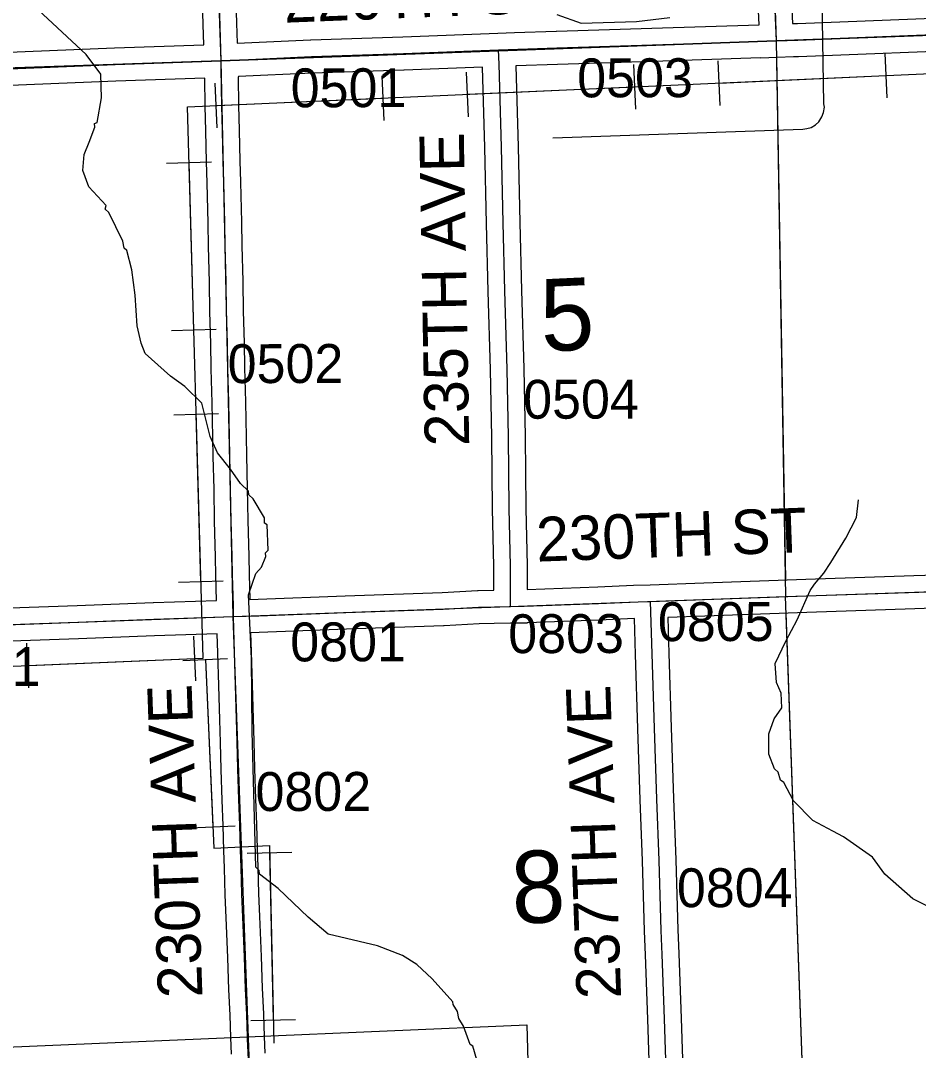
# Model space of a CAD drawing. Extents: x 128.7 to 185.5, y -21.4 to 12.6.
# Drawn here: x 146.826 to 148.442, y -9.105 to -7.251 of the extents above; entities that cross this region are included whole.
import ezdxf

# ---------------------------------------------------------------- set-up
doc = ezdxf.new("R2010")
doc.units = 0
for name, color, linetype in [('tdCoCityStreetMajor', 7, 'Continuous'), ('tdCoCorpBndry', 7, 'Continuous'), ('tdCoDirctArrow', 7, 'Continuous'), ('tdCoHydroRiver', 7, 'Continuous'), ('tdCoPipe', 7, 'Continuous'), ('tdCoSecRdNmbr', 7, 'Continuous'), ('tdCoSecRdTxt', 7, 'Continuous'), ('tdCoSecRteBand', 7, 'Continuous'), ('tdCoSecRteCL', 7, 'Continuous'), ('tdCoSectLine', 7, 'Continuous'), ('tdCoSectLinePart', 7, 'Continuous'), ('tdCoSectNmbr', 7, 'Continuous'), ('tdCoSurfAsphalt', 7, 'Continuous'), ('tdCoSurfGravel', 7, 'Continuous'), ('tdCoTwpBndryShd', 7, 'Continuous')]:
    doc.layers.add(name, color=color, linetype=linetype)

msp = doc.modelspace()

# ---------------------------------------------------------------- linework, layer by layer
at = {"layer": 'tdCoCityStreetMajor'}
msp.add_lwpolyline([(147.2541, -9.648), (147.254, -9.6415), (147.2536, -9.6294), (147.2528, -9.5999), (147.252, -9.5812), (147.2505, -9.5406), (147.2501, -9.5269), (147.2493, -9.4988), (147.2478, -9.4468), (147.2475, -9.4358), (147.2472, -9.423), (147.2462, -9.3809), (147.2445, -9.3207), (147.2417, -9.2576), (147.239, -9.1803), (147.2367, -9.133), (147.2343, -9.0837), (147.2342, -9.0804)], dxfattribs=at)
at = {"layer": 'tdCoCorpBndry'}
msp.add_lwpolyline([(146.2705, -10.129), (146.2661, -9.9803), (146.2641, -9.8974), (146.2456, -9.3614), (146.2436, -9.283), (146.2422, -9.2521), (146.239, -9.1399), (146.2385, -9.1228), (147.2342, -9.0804), (147.737, -9.0589), (147.7522, -9.6071), (147.7531, -9.6384), (147.7717, -10.312)], dxfattribs=at)
at = {"layer": 'tdCoDirctArrow'}
msp.add_lwpolyline([(147.7837, -7.4626), (148.2339, -7.4469), (148.2414, -7.4457), (148.2487, -7.4438), (148.2565, -7.439), (148.2626, -7.4333), (148.268, -7.4248), (148.2713, -7.417), (148.273, -7.4074), (148.272, -7.4011), (148.2668, -7.0998)], dxfattribs=at)
at = {"layer": 'tdCoHydroRiver'}
for points in [[(147.647, -9.1218), (147.6398, -9.0968), (147.635, -9.0938), (147.6229, -9.061), (147.6145, -9.0471), (147.6125, -9.0345), (147.6042, -9.0222), (147.6041, -9.0175), (147.5664, -8.9761), (147.5388, -8.9502), (147.513, -8.9337), (147.4682, -8.9162), (147.3791, -8.8954), (147.3434, -8.865), (147.2896, -8.8131), (147.2557, -8.7874), (147.2554, -8.7811), (147.2489, -8.775), (147.2425, -8.5306), (147.2414, -8.3996), (147.236, -8.2846), (147.249, -8.2463), (147.2596, -8.2349), (147.2669, -8.2157), (147.2667, -8.2094), (147.2713, -8.2045), (147.2698, -8.1588), (147.2649, -8.1558), (147.2646, -8.1464), (147.2446, -8.1123), (147.2364, -8.1047), (147.2362, -8.0984), (147.2216, -8.0846), (147.2034, -8.0584), (147.1803, -8.0292), (147.1667, -7.9996), (147.1521, -7.9401), (147.1211, -7.9096), (147.0953, -7.8915), (147.0498, -7.8504), (147.0428, -7.8317), (147.0355, -7.8004), (147.0321, -7.7452), (147.0259, -7.6997), (147.0169, -7.6652), (147.012, -7.6607), (147.01, -7.6481), (146.9846, -7.5969), (146.9781, -7.5908), (146.9795, -7.5844), (146.9484, -7.5507), (146.938, -7.5211), (146.9402, -7.4926), (146.9489, -7.4702), (146.9591, -7.443), (146.9589, -7.4367), (146.9636, -7.435), (146.9716, -7.3905), (146.9702, -7.348), (146.9438, -7.3125), (146.8575, -7.2317)], [(147.7913, -7.2403), (147.8347, -7.2562), (147.9344, -7.2528), (147.9944, -7.246)], [(148.4905, -8.8615), (148.4322, -8.8318), (148.3813, -8.7876), (148.3594, -8.7567), (148.3072, -8.7205), (148.2877, -8.7101), (148.252, -8.6906), (148.2172, -8.6553), (148.2, -8.6227), (148.1935, -8.6181), (148.1897, -8.604), (148.1831, -8.5979), (148.1725, -8.5713), (148.1725, -8.5349), (148.1824, -8.5077), (148.1959, -8.4883), (148.1951, -8.4615), (148.1866, -8.4428), (148.1839, -8.4082), (148.2031, -8.3681), (148.2239, -8.3296), (148.2474, -8.2767), (148.2549, -8.2654), (148.2716, -8.2459), (148.2846, -8.2263), (148.3115, -8.1828), (148.3308, -8.1458), (148.3344, -8.1141)]]:
    msp.add_lwpolyline(points, dxfattribs=at)
at = {"layer": 'tdCoPipe'}
for p, q in [((148.3859, -7.3904), (148.3823, -7.3099)), ((147.9331, -7.4107), (147.9294, -7.3302)), ((148.085, -7.4039), (148.0814, -7.3235)), ((147.4802, -7.4311), (147.4766, -7.3505)), ((147.6322, -7.4243), (147.6286, -7.3439)), ((147.1794, -7.4446), (147.1758, -7.3642)), ((147.1692, -7.506), (147.0886, -7.5083)), ((147.1777, -7.8071), (147.0973, -7.8094)), ((147.182, -7.9591), (147.1014, -7.9614)), ((147.1905, -8.2602), (147.1101, -8.2625)), ((146.8403, -8.4523), (146.8369, -8.3719)), ((147.1412, -8.4396), (147.1378, -8.3591)), ((147.118, -8.403), (147.1984, -8.3995)), ((147.1313, -8.7039), (147.2119, -8.7004)), ((147.2336, -8.7497), (147.3141, -8.7479)), ((147.2402, -9.0508), (147.3208, -9.049))]:
    msp.add_line(p, q, dxfattribs=at)
for points in [[(141.1601, -9.4052), (141.1224, -8.4625), (145.143, -8.3469), (145.1432, -8.4836), (145.1432, -8.4836), (147.1541, -8.3987), (147.1541, -8.3987), (147.1261, -7.4066), (149.2539, -7.3111), (149.2196, -6.4561), (150.4341, -6.4227), (150.6653, -6.4146), (150.7655, -6.4047), (150.7905, -6.3931), (150.9328, -6.2039), (151.0021, -6.1768), (151.0811, -6.1651), (151.2121, -6.1436), (151.4086, -6.1336), (151.5974, -6.1255), (151.7034, -6.1214)], [(148.0832, -7.3637), (148.3841, -7.3501)], [(147.6304, -7.384), (147.9312, -7.3705)], [(147.1776, -7.4043), (147.4784, -7.3908)], [(147.1374, -7.8082), (147.1289, -7.5072)], [(147.1502, -8.2613), (147.1417, -7.9603)], [(146.8386, -8.4121), (147.1395, -8.3993)], [(147.1463, -8.4013), (147.1463, -8.4013)], [(147.1583, -8.4013), (147.1733, -8.7407), (147.2736, -8.7357), (147.2815, -9.0919)], [(147.1583, -8.4013), (147.1716, -8.7021)], [(147.2739, -8.7488), (147.2805, -9.0499)]]:
    msp.add_lwpolyline(points, dxfattribs=at)
at = {"layer": 'tdCoSecRteBand'}
for points in [[(146.2091, -7.327), (146.3655, -7.3225), (146.617, -7.3146), (146.6171, -7.3146), (146.6172, -7.3146), (146.7166, -7.3119), (146.9946, -7.3006), (146.9946, -7.3006), (146.9947, -7.3006), (147.1555, -7.2947), (147.1541, -7.2581), (147.1541, -7.258), (147.1541, -7.2578), (147.1507, -7.1385)], [(147.2107, -7.1368), (147.2141, -7.256), (147.2154, -7.2921)], [(147.2154, -7.2921), (147.3477, -7.2858), (147.348, -7.2858), (147.3482, -7.2858), (147.5139, -7.2806), (147.6849, -7.2742), (147.7149, -7.273), (147.7149, -7.273), (147.79, -7.2702), (147.7901, -7.2702), (147.7902, -7.2702), (147.9623, -7.265), (148.1553, -7.2587), (148.1543, -7.2337)], [(148.2143, -7.2315), (148.2153, -7.2567), (148.2241, -7.2564), (148.5591, -7.2436)], [(148.5613, -7.3036), (148.2263, -7.3164), (148.2262, -7.3164), (148.2261, -7.3164), (148.2174, -7.3167), (148.1875, -7.3177), (148.1577, -7.3188), (148.1577, -7.3186), (148.1575, -7.3186), (147.9642, -7.325), (147.9642, -7.325), (147.9641, -7.325), (147.7921, -7.3302), (147.7172, -7.333), (147.7171, -7.333), (147.7212, -7.4783), (147.7212, -7.4784), (147.7212, -7.4785), (147.7242, -7.6148), (147.7276, -7.737), (147.7276, -7.737), (147.7276, -7.737), (147.7316, -7.8776), (147.7316, -7.8777), (147.7316, -7.8779), (147.7338, -7.9999), (147.7338, -8), (147.7338, -8.0001), (147.7355, -8.1292), (147.7375, -8.2322), (147.7375, -8.2325), (147.7375, -8.2328), (147.7375, -8.2749), (147.865, -8.2702), (147.9288, -8.2676), (147.9288, -8.2675), (147.929, -8.2675), (147.929, -8.2673), (147.9589, -8.2665), (148.0557, -8.2631), (148.0557, -8.2631), (148.0557, -8.2631), (148.2392, -8.2567), (148.2392, -8.2567), (148.2392, -8.2567), (148.4338, -8.25), (148.4338, -8.25), (148.4338, -8.25), (148.5512, -8.2461)], [(147.2384, -8.2929), (147.2533, -8.2924), (147.4101, -8.2867), (147.4101, -8.2867), (147.4101, -8.2867), (147.5849, -8.2808), (147.6484, -8.2772), (147.6489, -8.2771), (147.6494, -8.2771), (147.6775, -8.2764), (147.6775, -8.2331), (147.6755, -8.1303), (147.6755, -8.1302), (147.6755, -8.1301), (147.6738, -8.001), (147.6716, -7.8791), (147.6676, -7.7387), (147.6642, -7.6164), (147.6642, -7.6163), (147.6642, -7.6162), (147.6612, -7.4799), (147.6572, -7.3353), (147.516, -7.3405), (147.5159, -7.3406), (147.5158, -7.3406), (147.3504, -7.3457), (147.2177, -7.3521), (147.2177, -7.3524), (147.2177, -7.3524), (147.2177, -7.3524), (147.2173, -7.3525), (147.2182, -7.404), (147.219, -7.4485), (147.2205, -7.5042), (147.2215, -7.5418), (147.2215, -7.5419), (147.2215, -7.5419), (147.2232, -7.6143), (147.2242, -7.6564), (147.2242, -7.6564), (147.2242, -7.6564), (147.2256, -7.7205), (147.2256, -7.7206), (147.2256, -7.7208), (147.2264, -7.7742), (147.2279, -7.831), (147.2279, -7.8311), (147.2279, -7.8312), (147.2287, -7.8763), (147.2303, -7.9376), (147.2303, -7.9377), (147.2304, -7.9378), (147.2316, -8.0004), (147.2326, -8.0339), (147.2326, -8.034), (147.2326, -8.0342), (147.2338, -8.0932), (147.2338, -8.0932), (147.2338, -8.0933), (147.2349, -8.1507), (147.2365, -8.2151), (147.2365, -8.2152), (147.2365, -8.2153), (147.2371, -8.2484), (147.2384, -8.2929)], [(146.807, -8.3082), (146.9277, -8.304), (147.0645, -8.2986), (147.0646, -8.2986), (147.0647, -8.2986), (147.1785, -8.2949), (147.1772, -8.25), (147.1771, -8.2499), (147.1771, -8.2497), (147.1765, -8.2165), (147.1749, -8.1521), (147.1749, -8.152), (147.1749, -8.1519), (147.1739, -8.0944), (147.1726, -8.0356), (147.1716, -8.002), (147.1716, -8.0019), (147.1716, -8.0017), (147.1704, -7.9391), (147.1687, -7.8778), (147.1687, -7.8777), (147.1687, -7.8775), (147.1679, -7.8324), (147.1665, -7.7756), (147.1665, -7.7755), (147.1665, -7.7753), (147.1656, -7.7218), (147.1642, -7.6578), (147.1632, -7.6157), (147.1632, -7.6157), (147.1632, -7.6156), (147.1615, -7.5434), (147.1605, -7.5058), (147.1605, -7.5058), (147.1605, -7.5058), (147.1591, -7.4499), (147.1591, -7.4498), (147.1591, -7.4497), (147.1582, -7.4051), (147.1573, -7.3547), (146.997, -7.3605), (146.7188, -7.3719)], [(148.5532, -8.306), (148.4358, -8.31), (148.2413, -8.3166), (148.0578, -8.323), (147.9909, -8.3254), (147.9907, -8.3254), (147.9926, -8.3903), (147.9966, -8.5236), (148.0013, -8.6512), (148.0055, -8.7615), (148.0055, -8.7616), (148.0055, -8.7618), (148.0089, -8.8875), (148.0109, -8.9304), (148.0109, -8.9306), (148.0109, -8.9308), (148.0146, -9.0467), (148.0183, -9.1578)], [(147.9583, -9.1599), (147.9546, -9.0487), (147.9546, -9.0486), (147.9546, -9.0486), (147.9509, -8.9329), (147.949, -8.89), (147.9489, -8.8897), (147.9489, -8.8894), (147.9455, -8.7636), (147.9413, -8.6535), (147.9413, -8.6535), (147.9413, -8.6535), (147.9366, -8.5257), (147.9366, -8.5256), (147.9366, -8.5255), (147.9327, -8.3921), (147.9327, -8.3921), (147.9327, -8.3921), (147.9308, -8.3275), (147.8674, -8.3302), (147.8673, -8.3302), (147.8673, -8.3302), (147.7382, -8.3349), (147.7382, -8.335), (147.7375, -8.335), (147.7375, -8.3357), (147.7079, -8.3357), (147.6782, -8.3364), (147.6514, -8.3371), (147.588, -8.3408), (147.5876, -8.3408), (147.5873, -8.3408), (147.4122, -8.3467), (147.2554, -8.3524), (147.2553, -8.3524), (147.2553, -8.3524), (147.24, -8.3529), (147.2396, -8.3529), (147.2408, -8.3873), (147.2408, -8.3874), (147.2408, -8.3874), (147.2425, -8.4464), (147.2443, -8.5077), (147.2458, -8.5483), (147.2458, -8.5485), (147.2458, -8.5486), (147.247, -8.5973), (147.2486, -8.6523), (147.2501, -8.698), (147.2517, -8.7425), (147.2517, -8.7426), (147.2517, -8.7426), (147.2527, -8.7745), (147.2527, -8.7745), (147.2527, -8.7746), (147.2542, -8.8225), (147.2558, -8.8639), (147.2558, -8.8639), (147.2558, -8.8639), (147.2585, -8.9354), (147.2607, -8.9927), (147.2628, -9.0388), (147.2628, -9.039), (147.2628, -9.0392), (147.2641, -9.0794), (147.2651, -9.1094)], [(147.2052, -9.1113), (147.2042, -9.0813), (147.2028, -9.0413), (147.2008, -8.9952), (147.2008, -8.9952), (147.2008, -8.9951), (147.1985, -8.9378), (147.1985, -8.9377), (147.1985, -8.9377), (147.1959, -8.8662), (147.1942, -8.8247), (147.1942, -8.8246), (147.1942, -8.8244), (147.1928, -8.7764), (147.1917, -8.7446), (147.1901, -8.7001), (147.1901, -8.7), (147.1901, -8.7), (147.1887, -8.6541), (147.1887, -8.6541), (147.1887, -8.6541), (147.187, -8.599), (147.187, -8.5989), (147.187, -8.5989), (147.1858, -8.5503), (147.1843, -8.5098), (147.1843, -8.5097), (147.1843, -8.5096), (147.1825, -8.4482), (147.1825, -8.4481), (147.1825, -8.4481), (147.1809, -8.3892), (147.1797, -8.3549), (147.0667, -8.3585), (146.93, -8.364), (146.9299, -8.364), (146.9298, -8.364), (146.809, -8.3682)]]:
    msp.add_lwpolyline(points, dxfattribs=at)
at = {"layer": 'tdCoSecRteCL'}
for points in [[(148.1865, -7.2877), (148.1843, -7.2325), (148.1833, -7.1943), (148.1784, -7.0562), (148.1742, -6.9294), (148.1705, -6.8012), (148.1665, -6.6811), (148.1618, -6.5514), (148.1584, -6.4258), (148.1539, -6.2964), (148.1535, -6.2826)], [(147.1866, -7.3236), (147.1841, -7.257), (147.1807, -7.1376)], [(149.231, -8.7525), (149.23, -8.7125), (149.2266, -8.588), (149.2234, -8.4472), (149.2197, -8.3091), (149.2162, -8.1784), (149.2123, -8.0373), (149.2096, -7.9061), (149.2051, -7.7636), (149.2014, -7.6371), (149.1975, -7.4792), (149.1938, -7.3365), (149.1918, -7.2667), (149.1906, -7.2608), (149.1866, -7.2556), (149.1825, -7.2534), (149.1768, -7.2516), (149.0125, -7.2578), (148.7053, -7.2686), (148.5603, -7.2736), (148.2251, -7.2864), (148.1865, -7.2877)], [(147.6861, -7.3042), (147.7911, -7.3002), (147.9632, -7.295), (148.1865, -7.2877)], [(147.1866, -7.3236), (147.3492, -7.3157), (147.5149, -7.3106), (147.6861, -7.3042)], [(147.7075, -8.3057), (147.7075, -8.2328), (147.7055, -8.1297), (147.7038, -8.0005), (147.7016, -7.8784), (147.6976, -7.7379), (147.6942, -7.6155), (147.6912, -7.4792), (147.687, -7.3297), (147.6861, -7.3042)], [(146.18, -7.3579), (146.3665, -7.3525), (146.618, -7.3446), (146.7176, -7.3419), (146.9958, -7.3305), (147.1866, -7.3236)], [(147.2091, -8.3239), (147.2088, -8.3046), (147.2071, -8.2492), (147.2065, -8.2159), (147.2049, -8.1513), (147.2038, -8.0938), (147.2026, -8.0348), (147.2016, -8.0011), (147.2004, -7.9384), (147.1987, -7.877), (147.1979, -7.8318), (147.1965, -7.7749), (147.1956, -7.7212), (147.1942, -7.6571), (147.1932, -7.615), (147.1915, -7.5426), (147.1905, -7.505), (147.1891, -7.4491), (147.1882, -7.4045), (147.187, -7.3379), (147.1866, -7.3236)], [(147.9599, -8.2965), (148.0568, -8.2931), (148.2403, -8.2866), (148.4348, -8.28), (148.5522, -8.276)], [(147.7075, -8.3057), (147.732, -8.3051), (147.8661, -8.3002), (147.9374, -8.2972), (147.9599, -8.2965)], [(147.7531, -9.6384), (147.8537, -9.6358), (147.9635, -9.6338), (147.9857, -9.6341), (147.996, -9.6326), (148.0004, -9.63), (148.0024, -9.6236), (148.0036, -9.6162), (148.0044, -9.6088), (148.0041, -9.6035), (148.0036, -9.5949), (148.0014, -9.5439), (148.0004, -9.5182), (147.9967, -9.403), (147.993, -9.2844), (147.9883, -9.1589), (147.9846, -9.0477), (147.9809, -8.9318), (147.9789, -8.8886), (147.9755, -8.7626), (147.9713, -8.6524), (147.9666, -8.5246), (147.9627, -8.3912), (147.9599, -8.2965)], [(147.2091, -8.3239), (147.2543, -8.3224), (147.4112, -8.3167), (147.5863, -8.3108), (147.6501, -8.3071), (147.7075, -8.3057)], [(146.2136, -8.3605), (146.2886, -8.3574), (146.4181, -8.3527), (146.6482, -8.3439), (146.7157, -8.3411), (146.808, -8.3382), (146.9288, -8.334), (147.0657, -8.3286), (147.2091, -8.3239)], [(147.2342, -9.0804), (147.2328, -9.0401), (147.2308, -8.9939), (147.2285, -8.9366), (147.2258, -8.8651), (147.2242, -8.8235), (147.2228, -8.7755), (147.2217, -8.7436), (147.2201, -8.699), (147.2186, -8.6532), (147.217, -8.5981), (147.2158, -8.5494), (147.2143, -8.5087), (147.2125, -8.4473), (147.2108, -8.3883), (147.2094, -8.3464), (147.2091, -8.3239)]]:
    msp.add_lwpolyline(points, dxfattribs=at)
at = {"layer": 'tdCoSectLine'}
for points in [[(148.1531, -6.2826), (148.1861, -7.2877)], [(147.1565, -6.3208), (147.1862, -7.3236)], [(148.1861, -7.2877), (149.1912, -7.251)], [(147.1862, -7.3236), (148.1861, -7.2877)], [(148.1861, -7.2877), (148.203, -8.2879)], [(146.1796, -7.3579), (147.1862, -7.3236)], [(147.1862, -7.3236), (147.2075, -8.3239)], [(148.203, -8.2879), (149.2179, -8.2547)], [(147.2075, -8.3239), (148.203, -8.2879)], [(148.2385, -9.2881), (148.203, -8.2879)], [(146.2133, -8.3605), (147.2075, -8.3239)], [(147.2075, -8.3239), (147.2444, -9.3296)]]:
    msp.add_lwpolyline(points, dxfattribs=at)
at = {"layer": 'tdCoSectLinePart'}
for points in [[(148.1866, -7.3176), (148.2025, -8.2585)], [(148.2385, -9.2881), (148.2041, -8.3179)]]:
    msp.add_lwpolyline(points, dxfattribs=at)
at = {"layer": 'tdCoSurfAsphalt'}
msp.add_lwpolyline([(147.2342, -9.0804), (147.2328, -9.0401), (147.2308, -8.9939), (147.2285, -8.9366), (147.2258, -8.8651), (147.2242, -8.8235), (147.2228, -8.7755), (147.2217, -8.7436), (147.2201, -8.699), (147.2186, -8.6532), (147.217, -8.5981), (147.2158, -8.5494), (147.2143, -8.5087), (147.2125, -8.4473), (147.2108, -8.3883), (147.2094, -8.3464), (147.2091, -8.3239), (147.2088, -8.3046), (147.2071, -8.2492), (147.2065, -8.2159), (147.2049, -8.1513), (147.2038, -8.0938), (147.2026, -8.0348), (147.2016, -8.0011), (147.2004, -7.9384), (147.1987, -7.877), (147.1979, -7.8318), (147.1965, -7.7749), (147.1956, -7.7212), (147.1942, -7.6571), (147.1932, -7.615), (147.1915, -7.5426), (147.1905, -7.505), (147.1891, -7.4491), (147.1882, -7.4045), (147.187, -7.3379), (147.1866, -7.3236), (147.1841, -7.257), (147.1807, -7.1376)], dxfattribs=at)
at = {"layer": 'tdCoSurfGravel'}
for points in [[(148.1865, -7.2877), (148.1843, -7.2325), (148.1833, -7.1943), (148.1784, -7.0562), (148.1742, -6.9294), (148.1705, -6.8012), (148.1665, -6.6811), (148.1618, -6.5514), (148.1584, -6.4258), (148.1539, -6.2964), (148.1535, -6.2826)], [(148.1865, -7.2877), (148.2251, -7.2864), (148.5603, -7.2736), (148.7053, -7.2686), (149.0125, -7.2578), (149.1768, -7.2516), (149.1825, -7.2534), (149.1866, -7.2556)], [(147.1866, -7.3236), (147.3492, -7.3157), (147.5149, -7.3106), (147.6861, -7.3042), (147.7911, -7.3002), (147.9632, -7.295), (148.1865, -7.2877)], [(147.7075, -8.3057), (147.7075, -8.2328), (147.7055, -8.1297), (147.7038, -8.0005), (147.7016, -7.8784), (147.6976, -7.7379), (147.6942, -7.6155), (147.6912, -7.4792), (147.687, -7.3297), (147.6861, -7.3042)], [(146.18, -7.3579), (146.3665, -7.3525), (146.618, -7.3446), (146.7176, -7.3419), (146.9958, -7.3305), (147.1866, -7.3236)], [(146.808, -8.3382), (146.9288, -8.334), (147.0657, -8.3286), (147.2091, -8.3239), (147.2543, -8.3224), (147.4112, -8.3167), (147.5863, -8.3108), (147.6501, -8.3071), (147.7075, -8.3057), (147.732, -8.3051), (147.8661, -8.3002), (147.9374, -8.2972), (147.9599, -8.2965), (148.0568, -8.2931), (148.2403, -8.2866), (148.4348, -8.28), (148.5522, -8.276)], [(148.0041, -9.6035), (148.0036, -9.5949), (148.0014, -9.5439), (148.0004, -9.5182), (147.9967, -9.403), (147.993, -9.2844), (147.9883, -9.1589), (147.9846, -9.0477), (147.9809, -8.9318), (147.9789, -8.8886), (147.9755, -8.7626), (147.9713, -8.6524), (147.9666, -8.5246), (147.9627, -8.3912), (147.9599, -8.2965)]]:
    msp.add_lwpolyline(points, dxfattribs=at)
at = {"layer": 'tdCoTwpBndryShd'}
msp.add_lwpolyline([(150.395, -13.7476), (150.378, -13.2238), (150.3466, -12.2212), (150.3134, -11.2212), (150.2794, -10.2174), (150.245, -9.219), (150.2118, -8.2199), (150.1854, -7.2186), (149.1912, -7.251), (148.1861, -7.2877), (147.1862, -7.3236), (146.1796, -7.3579), (145.1769, -7.3938), (144.1761, -7.4248), (143.1728, -7.4558), (142.1753, -7.4874), (141.1678, -7.5201), (140.1762, -7.5484), (139.1499, -7.567), (138.1783, -7.5984), (137.1762, -7.6276), (136.1739, -7.6508), (135.1725, -7.6763), (134.1612, -7.6994)], dxfattribs=at)

# ---------------------------------------------------------------- texts
at = {"layer": 'tdCoSecRdNmbr'}
for s, rotation, p in [('0503', 0.1121, (147.8278, -7.3895)), ('0501', 0.1118, (147.312, -7.4074)), ('0502', 0.1117, (147.1985, -7.9038)), ('0504', 0.112, (147.7305, -7.9679)), ('0805', 0.1122, (147.9731, -8.3682)), ('0803', 0.112, (147.7037, -8.3898)), ('0801', 0.1118, (147.3112, -8.4046)), ('0701', 0.1112, (146.6534, -8.4492)), ('0802', 0.1117, (147.2486, -8.6739)), ('0804', 0.1122, (148.0073, -8.847))]:
    msp.add_text(s, height=0.07, rotation=rotation, dxfattribs=at).set_placement(p)
at = {"layer": 'tdCoSecRdTxt'}
for s, rotation, p in [('220TH ST', 2.2386, (147.3006, -7.2552)), ('235TH AVE', 91, (147.6334, -8.0169)), ('230TH ST', 2.0557, (147.7552, -8.2251)), ('230TH AVE', 92, (147.1532, -9.009)), ('237TH AVE', 92, (147.9069, -9.0106))]:
    msp.add_text(s, height=0.08, rotation=rotation, dxfattribs=at).set_placement(p)
at = {"layer": 'tdCoSectNmbr'}
for s, rotation, p in [('5', 2.6644, (147.764, -7.8471)), ('8', 2.6643, (147.7119, -8.8772))]:
    msp.add_text(s, height=0.13, rotation=rotation, dxfattribs=at).set_placement(p)

doc.saveas('drawing.dxf')
